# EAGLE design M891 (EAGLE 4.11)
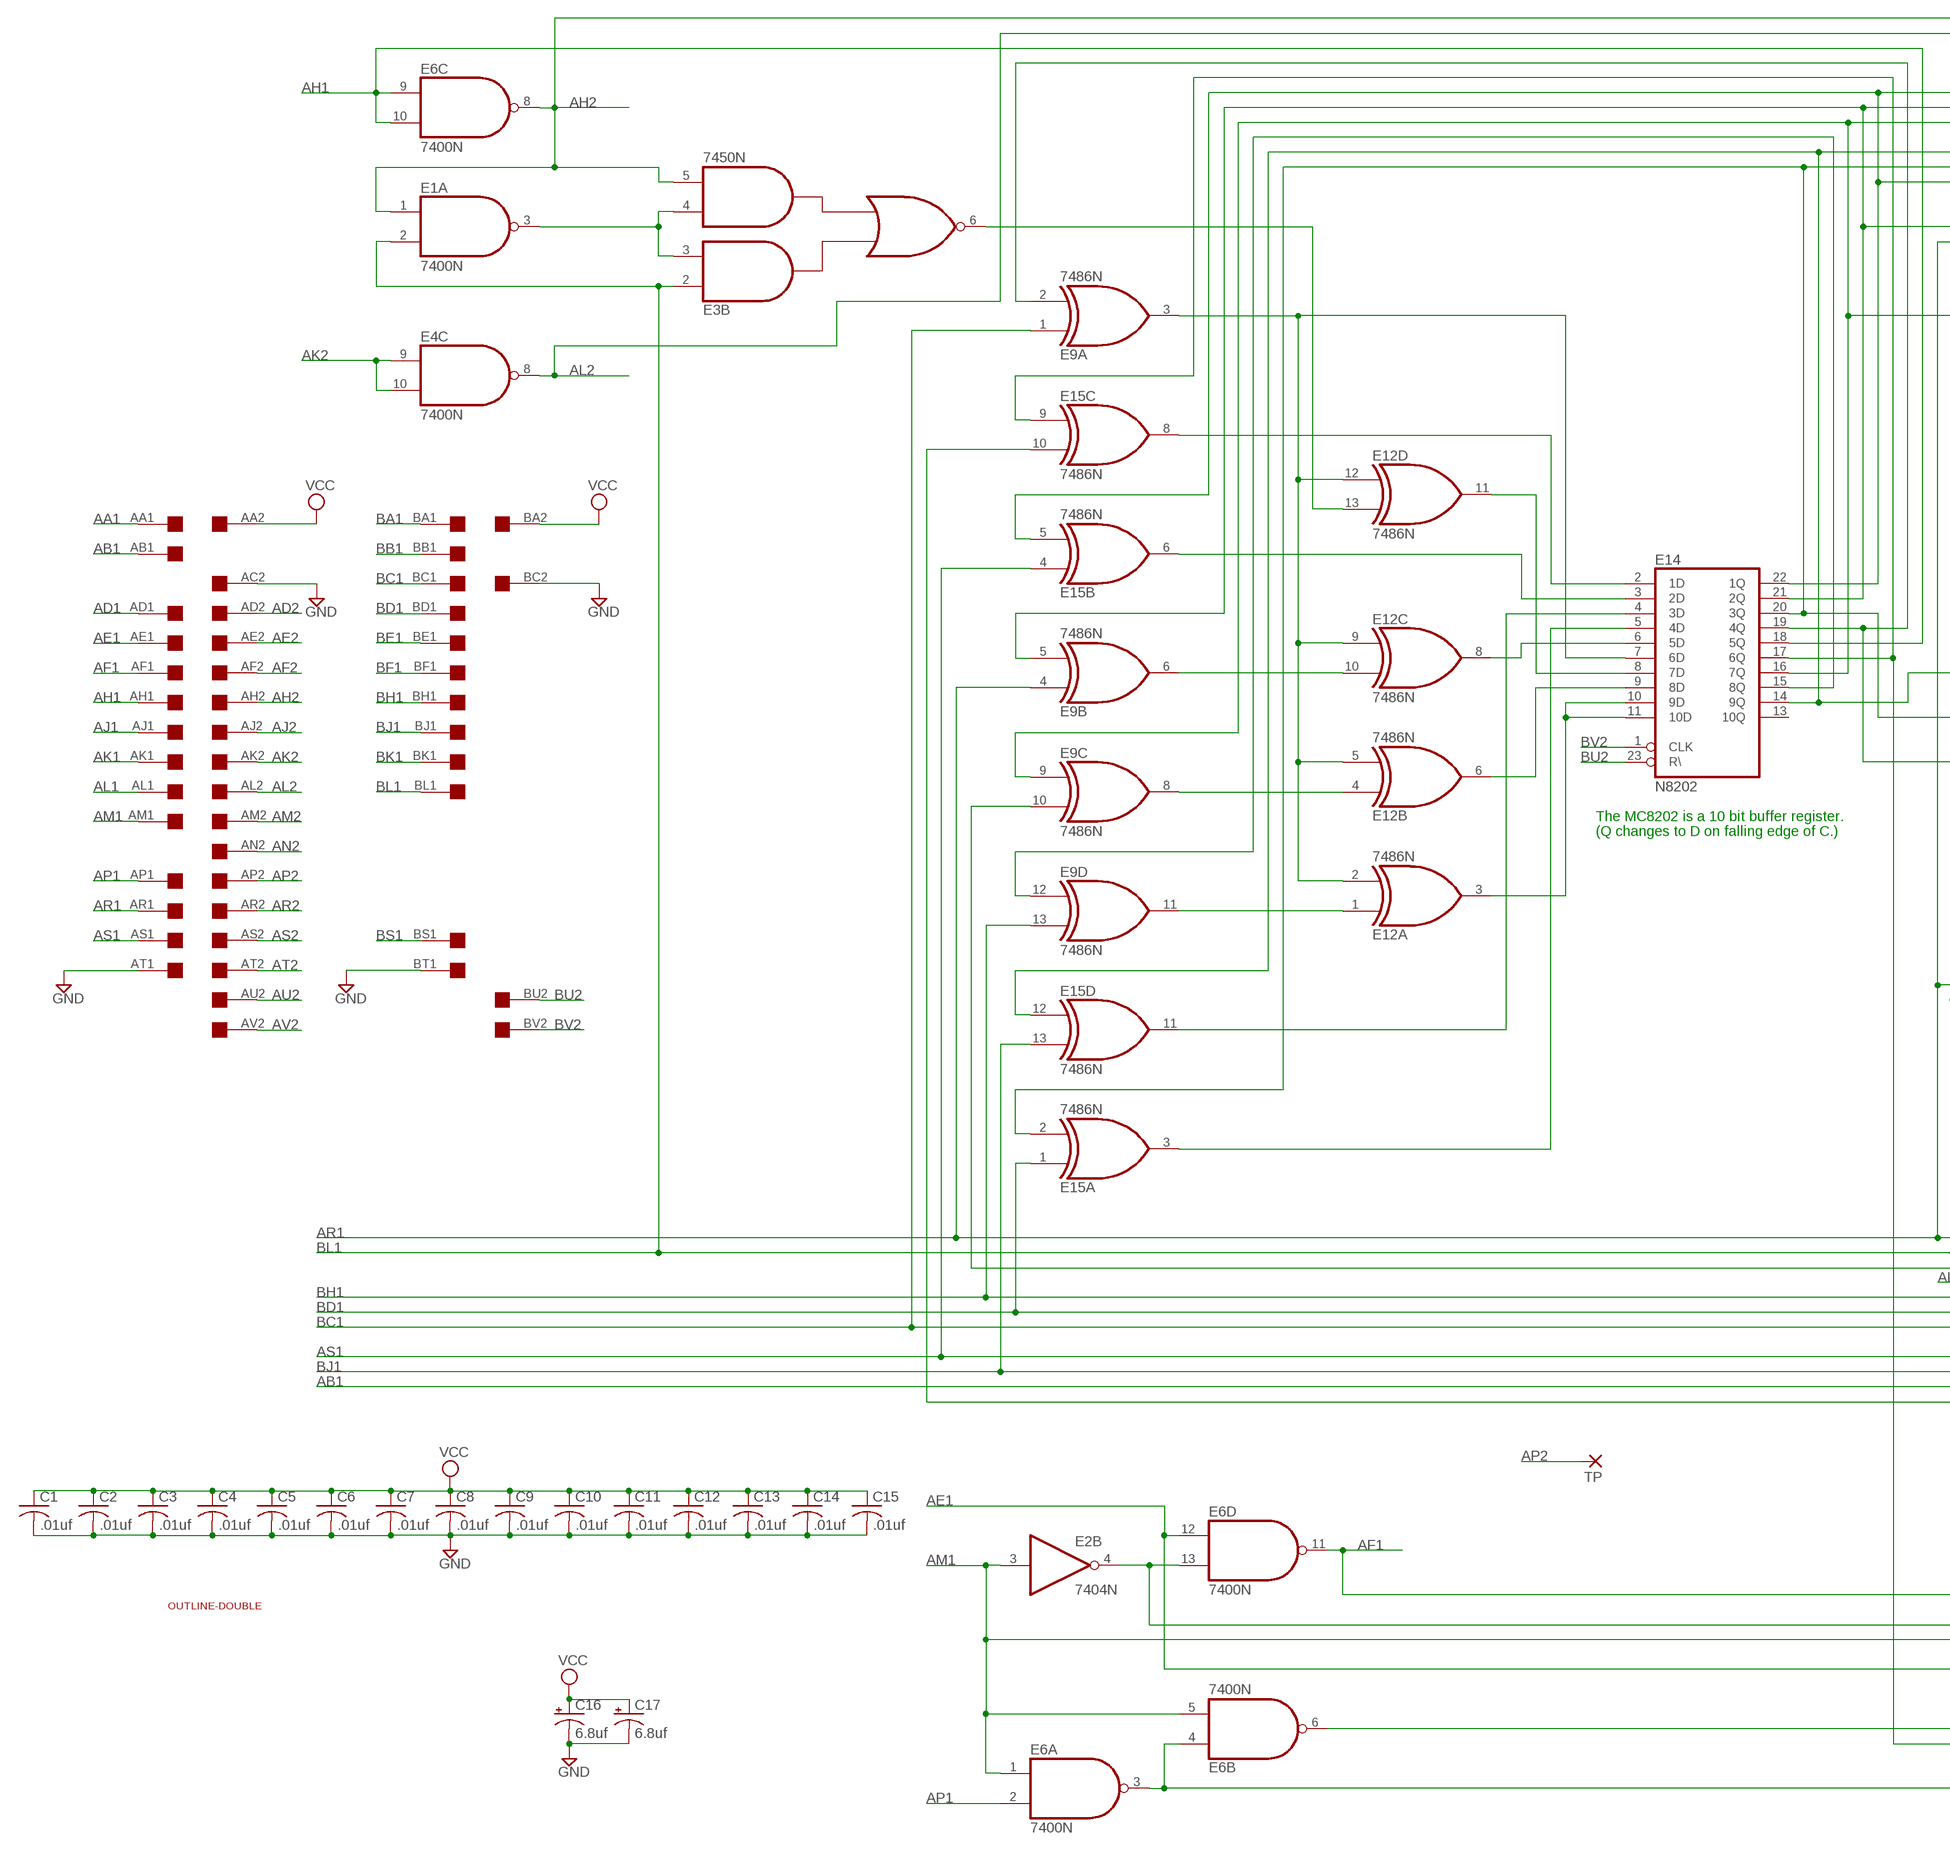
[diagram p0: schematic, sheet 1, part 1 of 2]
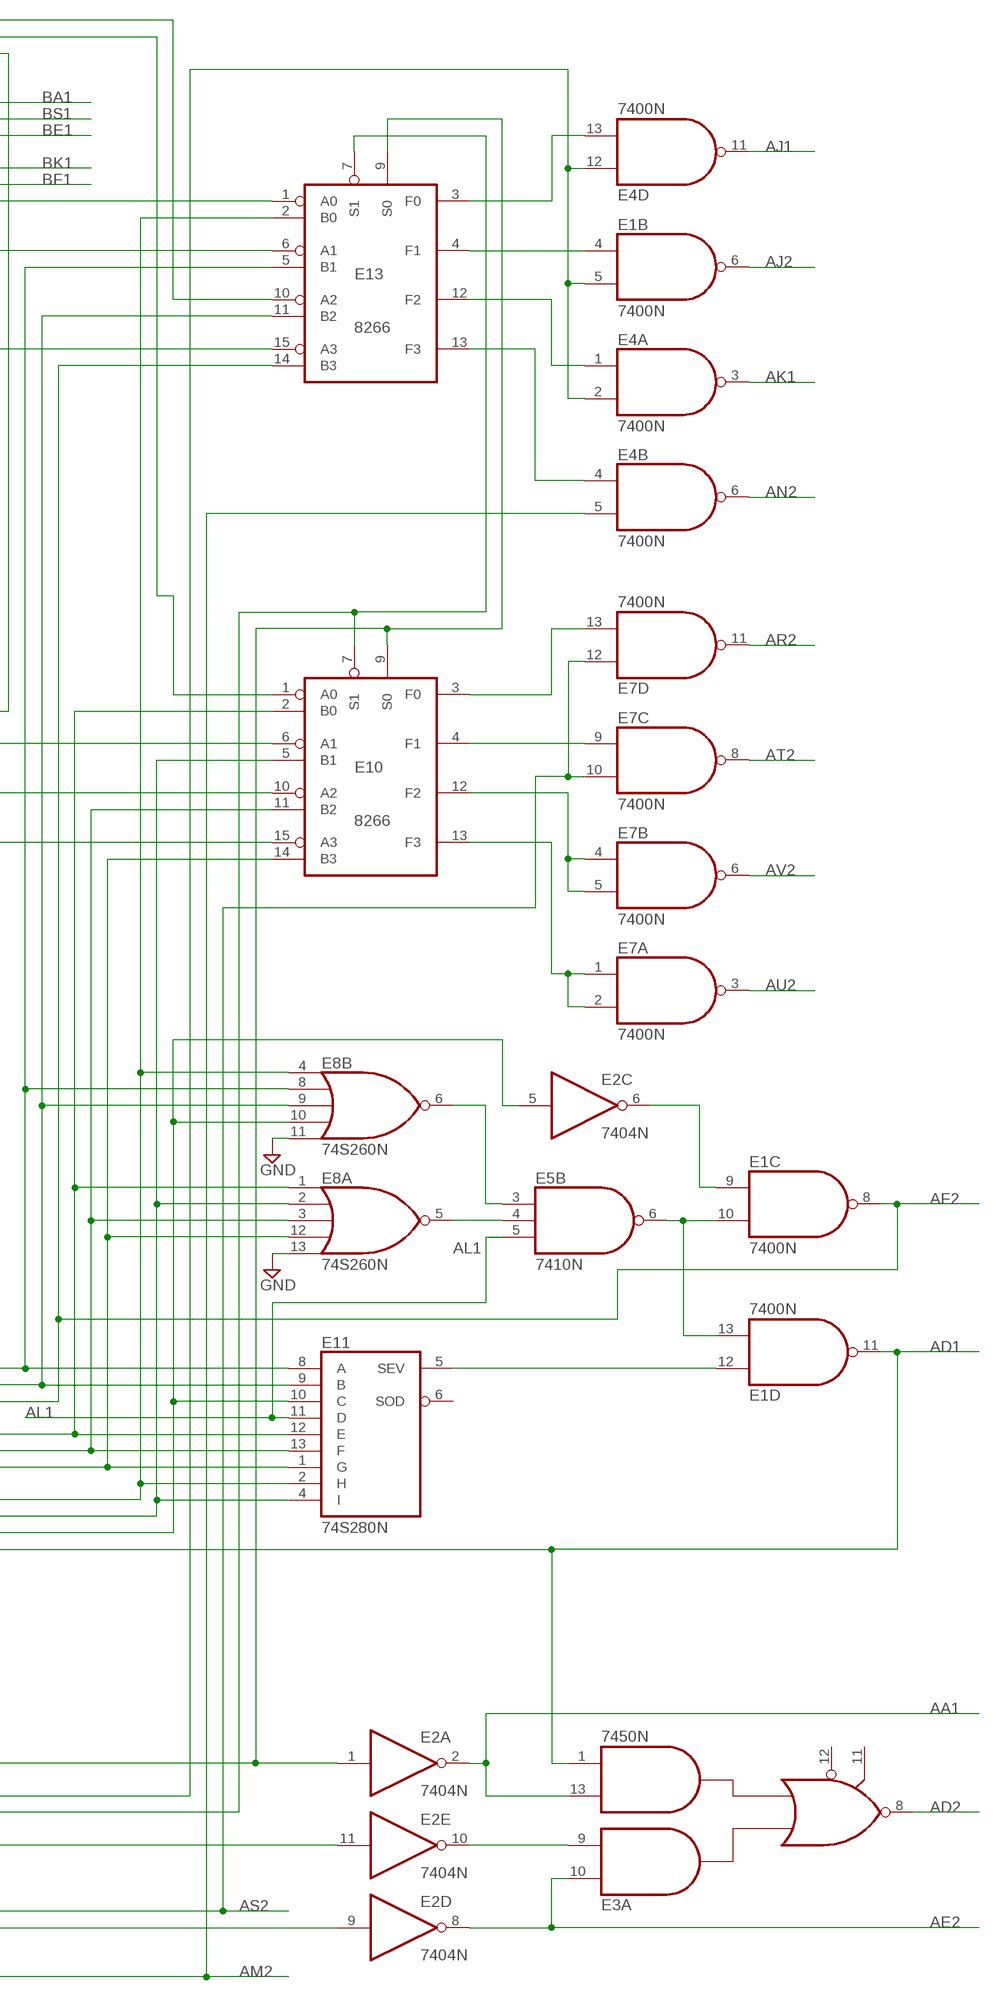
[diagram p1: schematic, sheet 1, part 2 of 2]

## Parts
C1  .01uf  C-US050-025X075  [C050-025X075]
C2  .01uf  C-US050-025X075  [C050-025X075]
C3  .01uf  C-US050-025X075  [C050-025X075]
C4  .01uf  C-US050-025X075  [C050-025X075]
C5  .01uf  C-US050-025X075  [C050-025X075]
C6  .01uf  C-US050-025X075  [C050-025X075]
C7  .01uf  C-US050-025X075  [C050-025X075]
C8  .01uf  C-US050-025X075  [C050-025X075]
C9  .01uf  C-US050-025X075  [C050-025X075]
C10  .01uf  C-US050-025X075  [C050-025X075]
C11  .01uf  C-US050-025X075  [C050-025X075]
C12  .01uf  C-US050-025X075  [C050-025X075]
C13  .01uf  C-US050-025X075  [C050-025X075]
C14  .01uf  C-US050-025X075  [C050-025X075]
C15  .01uf  C-US050-025X075  [C050-025X075]
C16  6.8uf  CPOL-USE22-6AXIAL  [E22-6]
C17  6.8uf  CPOL-USE22-6AXIAL  [E22-6]
E1  7400N  [DIL14]
E2  7404N  [DIL14]
E3  7450N  [DIL14]
E4  7400N  [DIL14]
E5  7410N  [DIL14]
E6  7400N  [DIL14]
E7  7400N  [DIL14]
E8  74S260N  [DIL14]
E9  7486N  [DIL14]
E10  8266  [DIL16]
E11  74S280N  [DIL14]
E12  7486N  [DIL14]
E13  8266  [DIL16]
E14  N8202  [DIL24]
E15  7486N  [DIL14]
EDGE  DOUBLE  [EDGE-CON4]
TP  2,15/1,0  [2,15/1,0]
U$2  OUTLINE-DOUBLE  [DOUBLE]

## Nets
AA1: E2.2(A:O) E3.13(A:I3) EDGE.AA1
AB1: E2.5(C:I) E8.10(B:I3) E11.10(C) EDGE.AB1
AD1: E1.11(D:O) E3.1(A:I4) E15.10(C:I1) EDGE.AD1
AD2: E3.8(A:O) EDGE.AD2
AE1: E2.11(E:I) E6.12(D:I0) EDGE.AE1
AE2: E2.8(D:O) E3.10(A:I1) EDGE.AE2
AF1: E2.1(A:I) E6.11(D:O) E10.9(S0) E13.9(S0) EDGE.AF1
AF2: E1.8(C:O) E9.10(C:I1) E13.14(B3) EDGE.AF2
AH1: E6.9(C:I0) E6.10(C:I1) E14.18(5Q) EDGE.AH1
AH2: E1.1(A:I0) E3.5(B:I4) E6.8(C:O) E13.10(A2) EDGE.AH2
AJ1: E4.11(D:O) EDGE.AJ1
AJ2: E1.6(B:O) EDGE.AJ2
AK1: E4.3(A:O) EDGE.AK1
AK2: E4.9(C:I0) E4.10(C:I1) EDGE.AK2
AL1: E5.5(B:I2) E11.11(D) EDGE.AL1
AL2: E4.8(C:O) E10.1(A0) EDGE.AL2
AM1: E2.3(B:I) E6.1(A:I0) E6.5(B:I1) E10.7(S1) E13.7(S1) EDGE.AM1
AM2: E4.5(B:I1) E6.3(A:O) E6.4(B:I0) EDGE.AM2
AN2: E4.6(B:O) EDGE.AN2
AP1: E6.2(A:I1) EDGE.AP1
AP2: EDGE.AP2 TP.1(P)
AR1: E8.8(B:I1) E9.4(B:I0) E11.8(A) E13.5(B1) EDGE.AR1
AR2: E7.11(D:O) EDGE.AR2
AS1: E8.4(B:I0) E11.2(H) E13.2(B0) E15.4(B:I0) EDGE.AS1
AS2: E6.6(B:O) E7.10(C:I1) E7.12(D:I0) EDGE.AS2
AT2: E7.8(C:O) EDGE.AT2
AU2: E7.3(A:O) EDGE.AU2
AV2: E7.6(B:O) EDGE.AV2
BA1: E13.1(A0) E14.22(1Q) E15.5(B:I1) EDGE.BA1
BB1: E9.2(A:I1) E10.15(A3) E14.19(4Q) EDGE.BB1
BC1: E8.12(A:I3) E9.1(A:I0) E10.14(B3) E11.1(G) EDGE.BC1
BD1: E8.3(A:I2) E10.11(B2) E11.13(F) E15.1(A:I0) EDGE.BD1
BE1: E9.9(C:I0) E13.15(A3) E14.16(7Q) EDGE.BE1
BF1: E10.10(A2) E14.20(3Q) E15.2(A:I1) EDGE.BF1
BH1: E8.1(A:I0) E9.13(D:I1) E10.2(B0) E11.12(E) EDGE.BH1
BJ1: E8.2(A:I1) E10.5(B1) E11.4(I) E15.13(D:I1) EDGE.BJ1
BK1: E10.6(A1) E14.14(9Q) E15.12(D:I0) EDGE.BK1
BL1: E1.2(A:I1) E3.2(B:I1) E8.9(B:I2) E11.9(B) E13.11(B2) EDGE.BL1
BS1: E9.5(B:I1) E13.6(A1) E14.21(2Q) EDGE.BS1
BU2: E14.23(R\) EDGE.BU2
BV2: E14.1(CLK) EDGE.BV2
GND [power]: C1.2 C2.2 C3.2 C4.2 C5.2 C6.2 C7.2 C8.2 C9.2 C10.2 C11.2 C12.2 C13.2 C14.2 C15.2 C16.- C17.- E8.11(B:I4) E8.13(A:I4) EDGE.AC2 EDGE.AT1 EDGE.BC2 EDGE.BT1
N$1: E1.3(A:O) E3.3(B:I2) E3.4(B:I3)
N$4: E2.9(D:I) E14.17(6Q) E15.9(C:I0)
N$5: E1.5(B:I1) E2.4(B:O) E4.2(A:I1) E4.12(D:I0) E6.13(D:I1)
N$6: E4.13(D:I1) E13.3(F0)
N$7: E1.4(B:I0) E13.4(F1)
N$8: E4.1(A:I0) E13.12(F2)
N$9: E4.4(B:I0) E13.13(F3)
N$10: E9.12(D:I0) E14.15(8Q)
N$11: E3.6(B:O) E12.13(D:I1)
N$12: E1.12(D:I0) E11.5(SEV)
N$13: E14.3(2D) E15.6(B:O)
N$14: E9.3(A:O) E12.2(A:I1) E12.5(B:I1) E12.9(C:I0) E12.12(D:I0) E14.7(6D)
N$15: E9.11(D:O) E12.1(A:I0)
N$16: E9.8(C:O) E12.4(B:I0)
N$17: E9.6(B:O) E12.10(C:I1)
N$18: E14.2(1D) E15.8(C:O)
N$19: E12.11(D:O) E14.8(7D)
N$20: E14.5(4D) E15.3(A:O)
N$21: E14.4(3D) E15.11(D:O)
N$22: E12.8(C:O) E14.6(5D)
N$23: E12.6(B:O) E14.9(8D)
N$24: E12.3(A:O) E14.10(9D) E14.11(10D)
N$25: E7.9(C:I0) E10.4(F1)
N$26: E7.13(D:I1) E10.3(F0)
N$27: E7.4(B:I0) E7.5(B:I1) E10.12(F2)
N$28: E7.1(A:I0) E7.2(A:I1) E10.13(F3)
N$33: E2.10(E:O) E3.9(A:I2)
N$43: E5.4(B:I1) E8.5(A:O)
N$44: E5.3(B:I0) E8.6(B:O)
N$45: E1.10(C:I1) E1.13(D:I1) E5.6(B:O)
N$46: E1.9(C:I0) E2.6(C:O)
VCC [power]: C1.1 C2.1 C3.1 C4.1 C5.1 C6.1 C7.1 C8.1 C9.1 C10.1 C11.1 C12.1 C13.1 C14.1 C15.1 C16.+ C17.+ EDGE.AA2 EDGE.BA2
Unconnected: E2.12(F:O) E2.13(F:I) E3.11(A:I6) E3.12(A:I5) E5.1(A:I0) E5.2(A:I1) E5.8(C:O) E5.9(C:I0) E5.10(C:I1) E5.11(C:I2) E5.12(A:O) E5.13(A:I2) E11.6(SOD) E14.13(10Q) EDGE.AB2 EDGE.AC1 EDGE.AN1 EDGE.AU1 EDGE.AV1 EDGE.BB2 EDGE.BD2 EDGE.BE2 EDGE.BF2 EDGE.BH2 EDGE.BJ2 EDGE.BK2 EDGE.BL2 EDGE.BM1 EDGE.BM2 EDGE.BN1 EDGE.BN2 EDGE.BP1 EDGE.BP2 EDGE.BR1 EDGE.BR2 EDGE.BS2 EDGE.BT2 EDGE.BU1 EDGE.BV1

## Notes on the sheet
- The MC8202 is a 10 bit buffer register.
- (Q changes to D on falling edge of C.)

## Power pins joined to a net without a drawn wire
GND: E1.7(P:GND) E2.7(P:GND) E3.7(P:GND) E4.7(P:GND) E5.7(P:GND) E6.7(P:GND) E7.7(P:GND) E8.7(P:GND) E9.7(P:GND) E10.8(GND) E11.7(GND) E12.7(P:GND) E13.8(GND) E14.12(GND) E15.7(P:GND)
VCC: E1.14(P:VCC) E2.14(P:VCC) E3.14(P:VCC) E4.14(P:VCC) E5.14(P:VCC) E6.14(P:VCC) E7.14(P:VCC) E8.14(P:VCC) E9.14(P:VCC) E10.16(VCC) E11.14(VCC) E12.14(P:VCC) E13.16(VCC) E14.24(VCC) E15.14(P:VCC)

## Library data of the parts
C1-C15 = rcl:C-US: CAPACITOR, American symbol
C16 C17 = rcl:CPOL-US: POLARIZED CAPACITOR, American symbol
E1 E4 E6 E7 = 74xx-jameco:74*00: Quad 2-input NAND gate
E2 = 74xx-jameco:74*04: Hex INVERTER
E3 = 74xxN:74*50: 4-2-3-2 input AND OR INVERTER gates
E5 = 74xx-jameco:74*10: Triple 3-input NAND gate
E8 = 74xx-jameco:74*260: Dual 5-input positive NOR gate
E9 E12 E15 = 74xx-jameco:74*86: Quad 2-input EXCLUSIV-OR (XOR) gate
E10 E13 = dec-con:8266: Quad 2-1 selector
E11 = 74xx-jameco:74*280: 9-bit odd/even PARITY GENERATOR/CHECKER
E14 = dec-con:N8202: 10 bit register
EDGE = dec-con:DOUBLE: Double-Height DEC board
TP = wirepad:2,15/1,0: THROUGH-HOLE PAD
U$2 = dec-con:OUTLINE-*: Board outlines for DEC boards.

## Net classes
1 power: width 0.508 mm

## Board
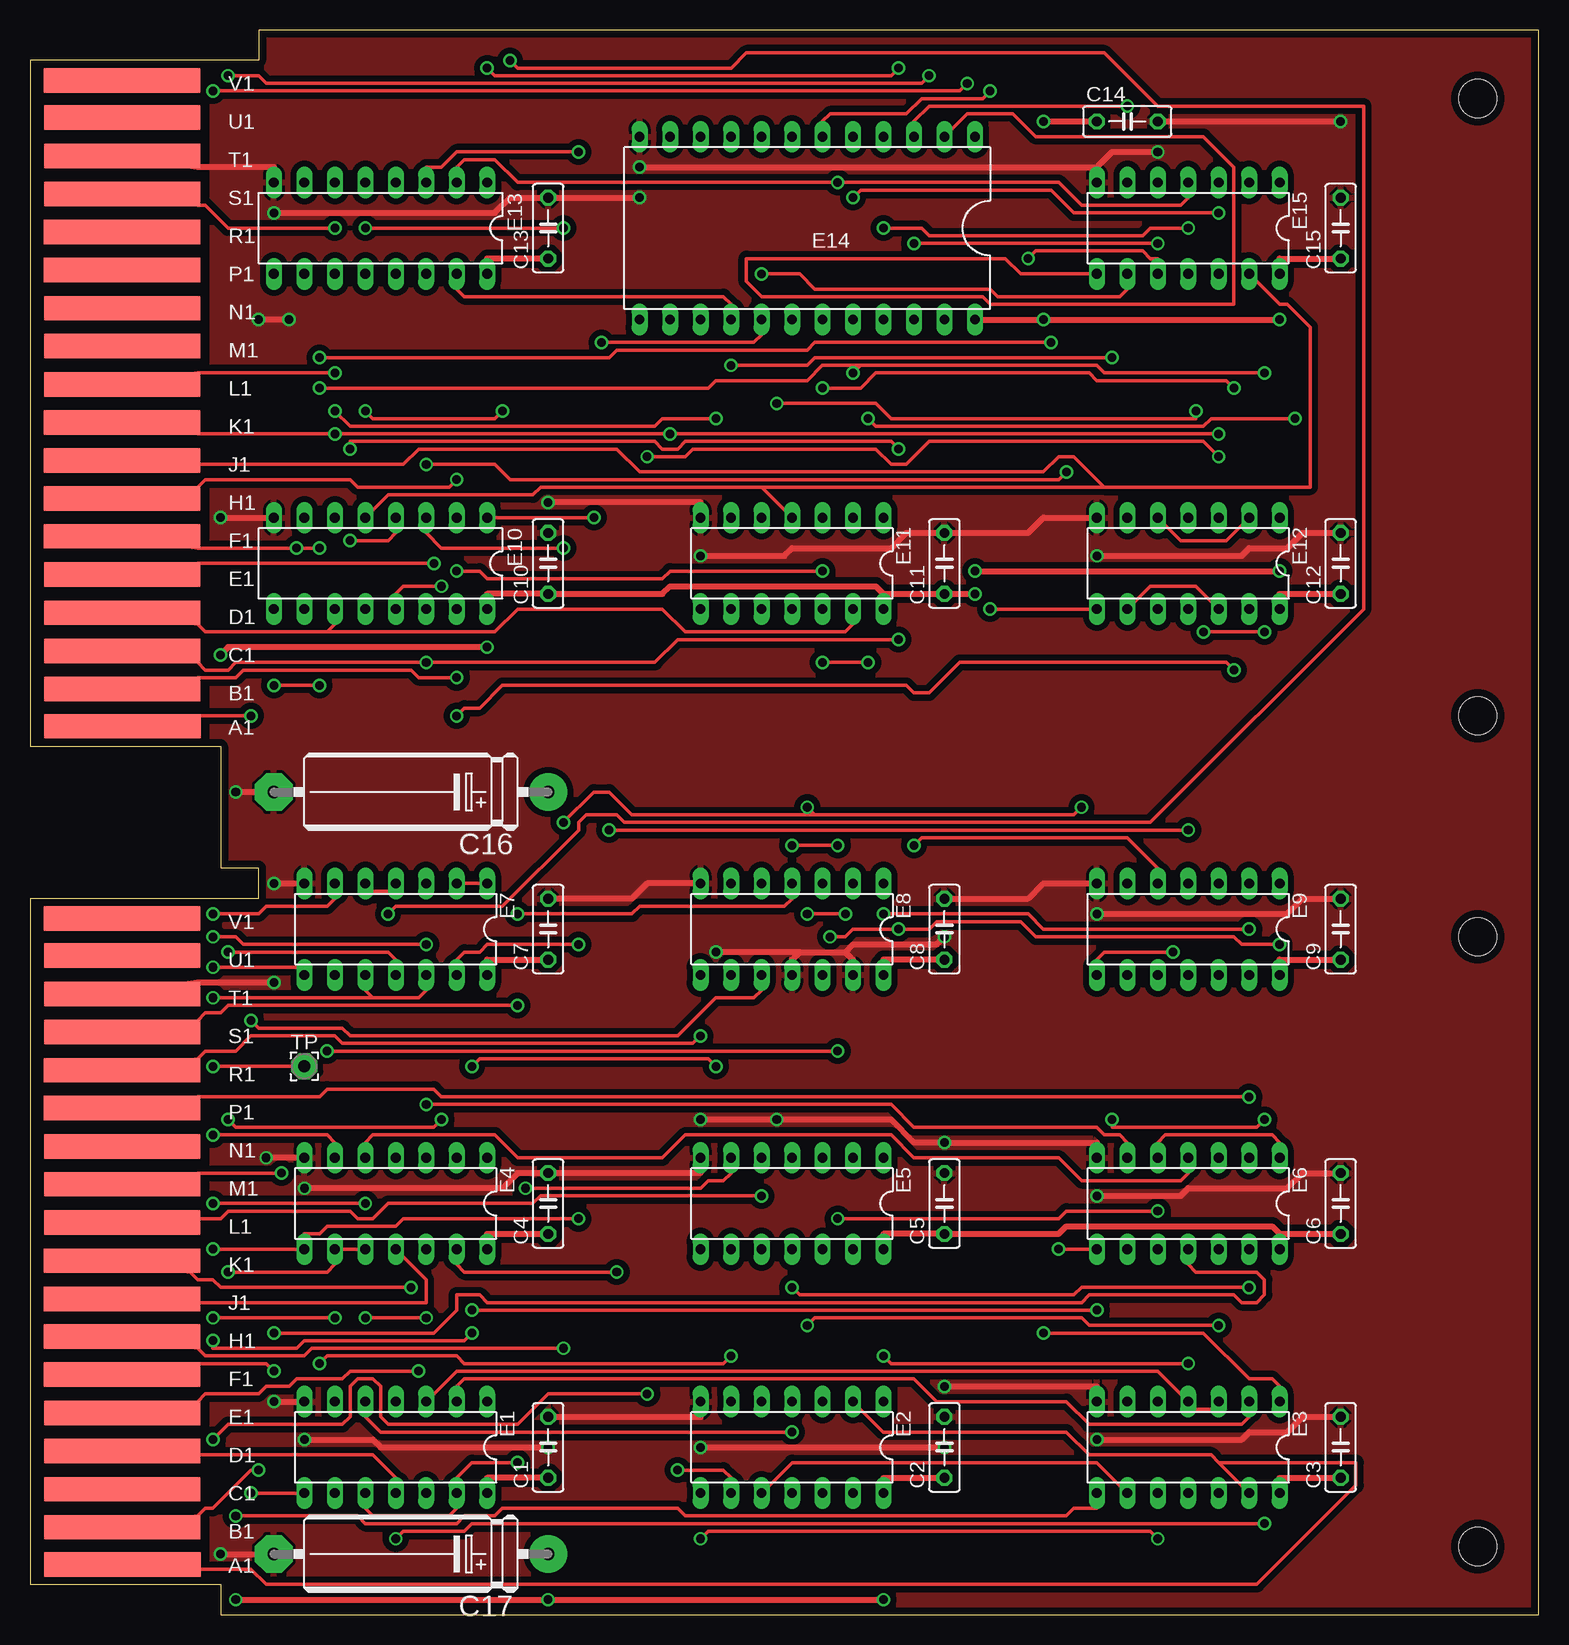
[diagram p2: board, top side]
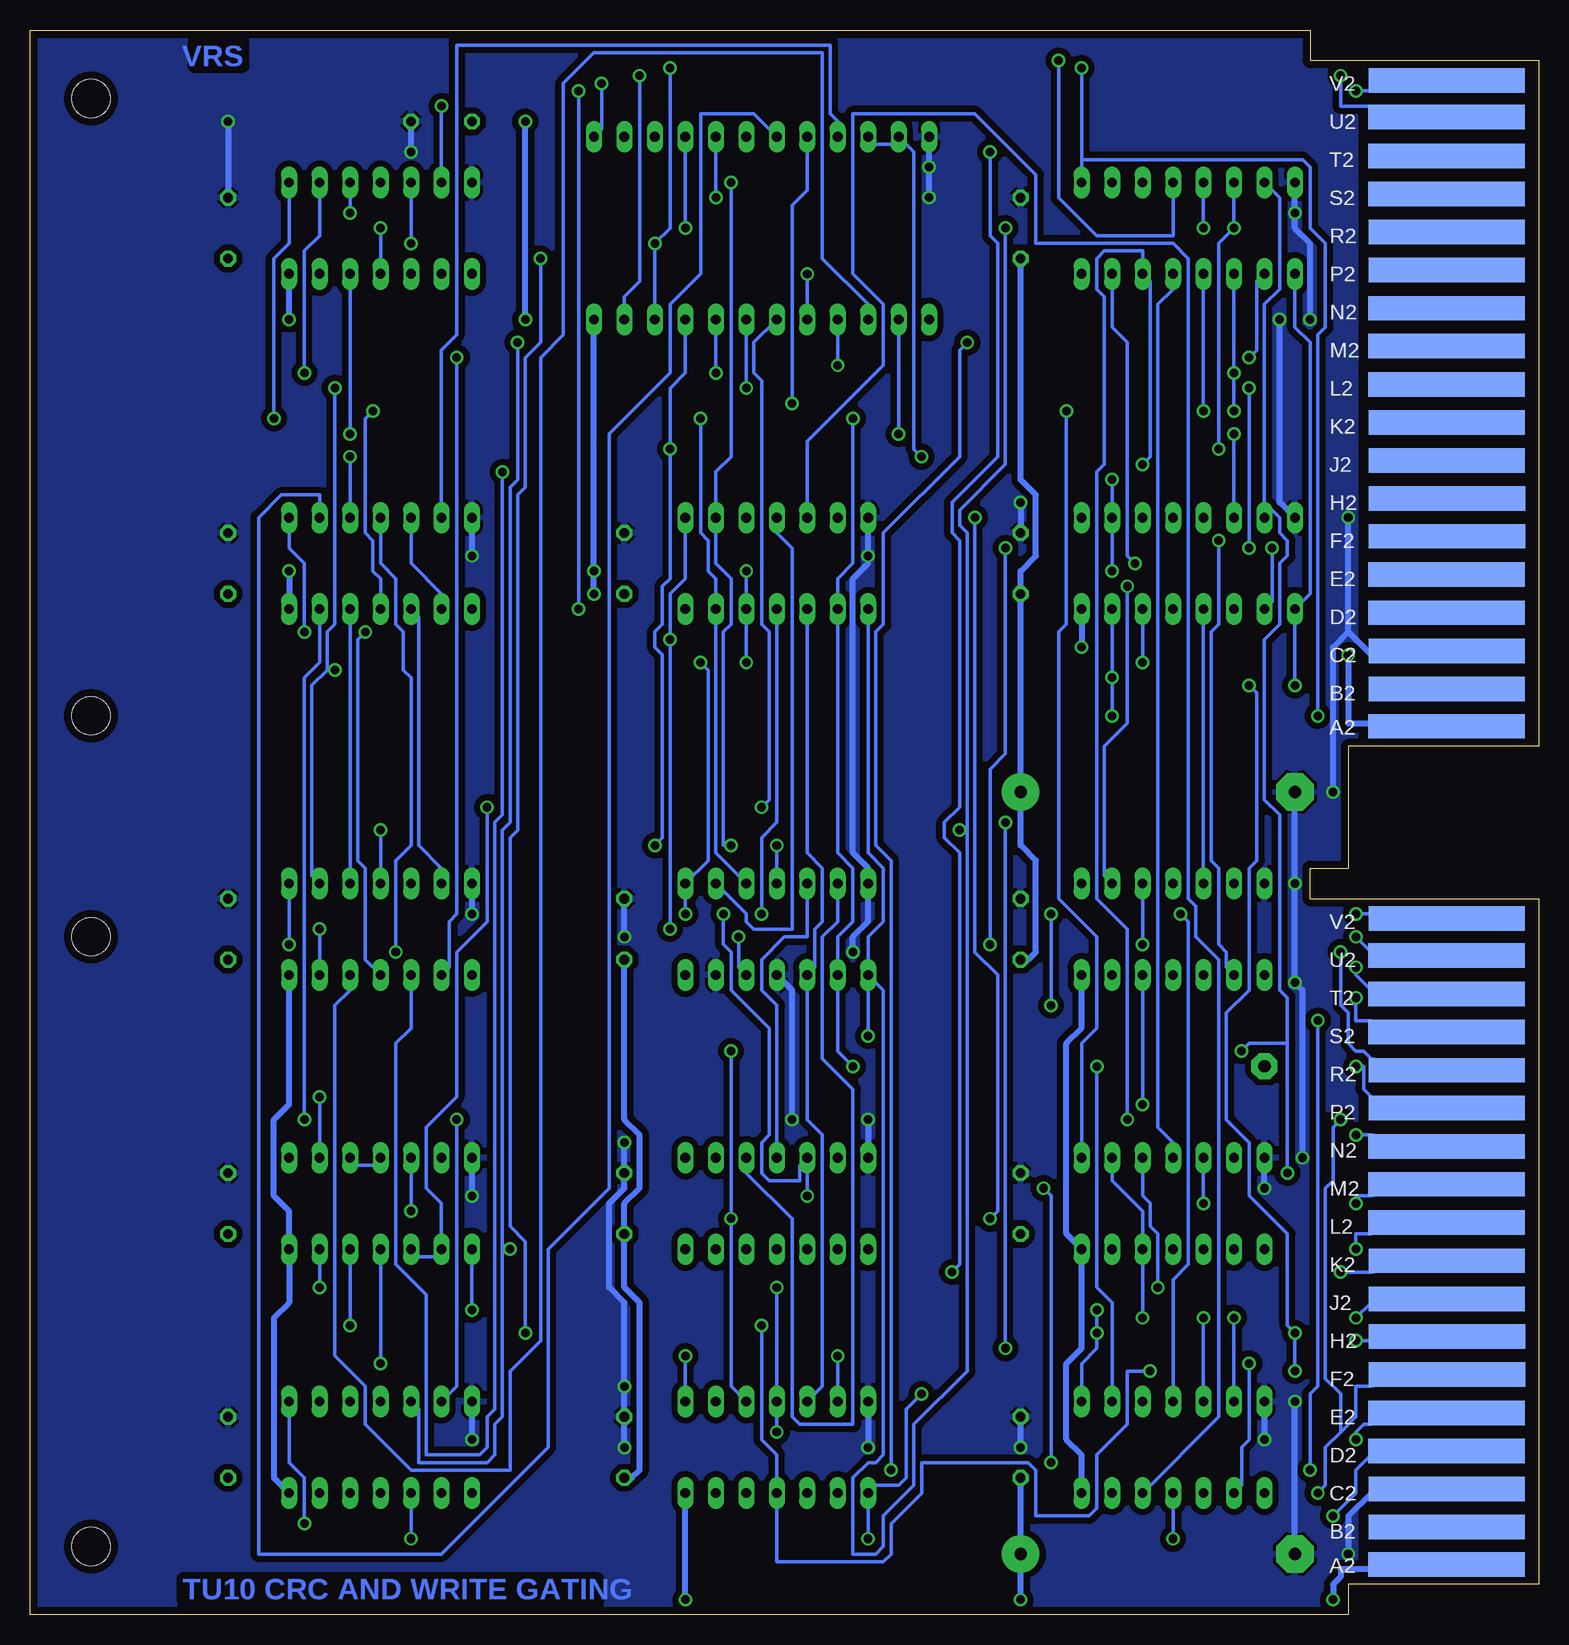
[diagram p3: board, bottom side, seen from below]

Size 125.73 x 132.08 mm. Coordinates in mm from the lower left corner, seen from the top.
Copper layers (1*16): Top 0.035mm / dielectric 1.5mm / Bottom 0.035mm
Design rules "10mils": minimum track width 12mil, minimum drill 28mil, track to track 10mil, track to pad 10mil, pad to pad 10mil, via to via 10mil, smd to smd 10mil, copper to edge 25mil, drill to drill 10mil, minimum pad ring 10mil, minimum via ring 8mil, stop-mask expansion 0mil, vias tented up to drill 0mil, thermal gap 10mil

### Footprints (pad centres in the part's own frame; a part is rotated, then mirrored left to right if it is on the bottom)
C050-025X075 = drill 0.813 octagon: 1 -2.54,0; 2 2.54,0
E22-6 = drill 1.016 pad 3.15 round: + -11.43,0 | drill 1.016 pad 3.15 octagon: - 11.43,0
DIL14 = drill 0.813 long: 1 -7.62,-3.81; 2 -5.08,-3.81; 3 -2.54,-3.81; 4 0,-3.81; 5 2.54,-3.81; 6 5.08,-3.81; 7 7.62,-3.81; 8 7.62,3.81; 9 5.08,3.81; 10 2.54,3.81; 11 0,3.81; 12 -2.54,3.81; 13 -5.08,3.81; 14 -7.62,3.81
DIL16 = drill 0.813 long: 1 -8.89,-3.81; 2 -6.35,-3.81; 3 -3.81,-3.81; 4 -1.27,-3.81; 5 1.27,-3.81; 6 3.81,-3.81; 7 6.35,-3.81; 8 8.89,-3.81; 9 8.89,3.81; 10 6.35,3.81; 11 3.81,3.81; 12 1.27,3.81; 13 -1.27,3.81; 14 -3.81,3.81; 15 -6.35,3.81; 16 -8.89,3.81
DIL24 = drill 0.813 long: 1 -12.7,-7.62; 2 -10.16,-7.62; 3 -7.62,-7.62; 4 -5.08,-7.62; 5 -2.54,-7.62; 6 0,-7.62; 7 2.54,-7.62; 8 5.08,-7.62; 9 7.62,-7.62; 10 10.16,-7.62; 11 12.7,-7.62; 12 15.24,-7.62; 13 15.24,7.62; 14 12.7,7.62; 15 10.16,7.62; 16 7.62,7.62; 17 5.08,7.62; 18 2.54,7.62; 19 0,7.62; 20 -2.54,7.62; 21 -5.08,7.62; 22 -7.62,7.62; 23 -10.16,7.62; 24 -12.7,7.62
EDGE-CON4 = smd 13.017 x 2.032: AA1 7.709,4.207; AB1 7.684,7.312; AC1 7.684,10.474; AD1 7.684,13.665; AE1 7.693,16.84; AF1 7.668,20.041; AH1 7.668,23.19; AJ1 7.668,26.34; AK1 7.668,29.515; AL1 7.693,32.69; AM1 7.693,35.89; AN1 7.693,39.04; AP1 7.668,42.24; AR1 7.668,45.39; AS1 7.693,48.565; AT1 7.693,51.74; AU1 7.693,54.94; AV1 7.668,58.026; BA1 7.709,74.057; BB1 7.684,77.162; BC1 7.684,80.324; BD1 7.684,83.515; BE1 7.693,86.69; BF1 7.668,89.891; BH1 7.668,93.04; BJ1 7.668,96.19; BK1 7.668,99.365; BL1 7.693,102.54; BM1 7.693,105.74; BN1 7.693,108.89; BP1 7.668,112.09; BR1 7.668,115.24; BS1 7.693,118.415; BT1 7.693,121.59; BU1 7.693,124.79; BV1 7.668,127.876 | smd 13.017 x 2.032 bottom: AA2 7.69,4.207; AB2 7.668,7.328; AC2 7.668,10.49; AD2 7.693,13.665; AE2 7.693,16.84; AF2 7.642,20.041; AH2 7.642,23.19; AJ2 7.668,26.34; AK2 7.668,29.515; AL2 7.693,32.69; AM2 7.693,35.89; AN2 7.693,39.04; AP2 7.668,42.24; AR2 7.668,45.39; AS2 7.693,48.565; AT2 7.693,51.74; AU2 7.693,54.966; AV2 7.668,58.026; BA2 7.69,74.057; BB2 7.668,77.178; BC2 7.668,80.34; BD2 7.693,83.515; BE2 7.693,86.69; BF2 7.642,89.891; BH2 7.642,93.04; BJ2 7.668,96.19; BK2 7.668,99.365; BL2 7.693,102.54; BM2 7.693,105.74; BN2 7.693,108.89; BP2 7.668,112.09; BR2 7.668,115.24; BS2 7.693,118.415; BT2 7.693,121.59; BU2 7.693,124.816; BV2 7.668,127.876
2,15/1,0 = drill 1.016 pad 2.159 octagon: 1 0,0
DOUBLE = hole 3.175: 120.65,56.515; 120.65,5.715; 120.65,74.93; 120.65,126.365

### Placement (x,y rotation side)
C1  43.18,13.97 90 top
C2  76.2,13.97 90 top
C3  109.22,13.97 90 top
C4  43.18,34.29 90 top
C5  76.2,34.29 90 top
C6  109.22,34.29 90 top
C7  43.18,57.15 90 top
C8  76.2,57.15 90 top
C9  109.22,57.15 90 top
C10  43.18,87.63 90 top
C11  76.2,87.63 90 top
C12  109.22,87.63 90 top
C13  43.18,115.57 90 top
C14  91.44,124.46 0 top
C15  109.22,115.57 90 top
C16  31.75,68.58 180 top
C17  31.75,5.08 180 top
E1  30.48,13.97 180 top
E2  63.5,13.97 180 top
E3  96.52,13.97 180 top
E4  30.48,34.29 180 top
E5  63.5,34.29 180 top
E6  96.52,34.29 180 top
E7  30.48,57.15 180 top
E8  63.5,57.15 180 top
E9  96.52,57.15 180 top
E10  29.21,87.63 180 top
E11  63.5,87.63 180 top
E12  96.52,87.63 180 top
E13  29.21,115.57 180 top
E14  66.04,115.57 180 top
E15  96.52,115.57 180 top
EDGE  0,0 0 top
TP  22.86,45.72 0 top
U$2  0,0 0 top

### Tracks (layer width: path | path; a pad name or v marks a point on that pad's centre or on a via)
AA1
  Top 0.305: 99.06,12.7 98.43,13.34 88.27,13.34 86.36,15.24 71.12,15.24 E2.2 | 99.06,12.7 E3.13 | 99.06,12.7 110.49,12.7 110.49,10.79 102.24,2.54 19.69,2.54 18.42,3.81 13.97,3.81 EDGE.AA1
AB1  (via drill 0.71)
  Top 0.305: v19.05,12.06 18.42,12.06 15.24,8.89 14.61,8.89 13.97,8.26 EDGE.AB1 | v18.42,49.53 19.05,48.9 26.04,48.9 26.67,48.26 53.98,48.26 57.15,51.44 60.33,51.44 60.96,52.07 E8.10
  Bottom 0.305: v19.05,12.06 19.05,18.41 18.42,19.05 v18.42,49.53 | E2.5 59.69,19.05 59.69,40.01 60.96,41.27 E8.10 60.33,53.98 60.33,57.15 59.69,57.78 59.69,62.23 60.96,63.5 E11.10
AD1  (via drill 0.71)
  Top 0.305: E1.11 30.48,11.43 28.58,13.34 13.97,13.34 EDGE.AD1 | v102.87,7.62 36.83,7.62 36.2,6.99 31.12,6.99 v30.48,6.35 | v83.19,113.03 83.82,113.67 92.71,113.67 93.35,113.03 93.98,113.03 E15.10 | v84.46,23.5 97.79,23.5 101.6,19.68 103.51,19.68 104.14,19.05 E3.1
  Bottom 0.305: v102.87,7.62 102.87,11.43 104.14,12.7 E3.1 | E1.11 v30.48,6.35 | v83.19,113.03 83.19,106.05 84.46,104.78 84.46,93.98 85.09,93.34 85.09,65.41 85.73,64.77 85.73,32.38 84.46,31.11 v84.46,23.5
AD2  (via drill 0.71)
  Top 0.305: v17.15,8.26 27.31,8.26 27.94,7.62 35.56,7.62 36.2,8.26 38.74,8.26 39.37,8.89 53.98,8.89 54.61,8.26 86.36,8.26 87,8.89 88.9,8.89 E3.8
  Bottom 0.305: v17.15,8.26 15.24,10.16 15.24,12.06 13.97,13.34 EDGE.AD2
AE1  (via drill 0.71)
  Top 0.305: v32.39,20.32 26.67,20.32 26.04,19.68 22.23,19.68 21.59,19.05 19.69,19.05 19.05,18.41 14.61,18.41 13.97,17.78 EDGE.AE1 | v99.06,24.13 88.27,24.13 87.63,24.77 65.41,24.77 v64.77,24.13
  Bottom 0.305: v32.39,20.32 34.29,20.32 34.29,15.88 36.83,13.34 36.83,8.89 37.47,8.26 41.91,8.26 41.91,12.06 42.55,12.7 51.44,12.7 51.44,10.16 53.98,7.62 53.98,5.08 54.61,4.45 63.5,4.45 E2.11 63.5,13.34 64.77,14.61 v64.77,24.13 | v99.06,24.13 E6.12
AE2  (via drill 0.71)
  Top 0.305: v15.24,14.61 16.51,15.88 26.04,15.88 26.67,16.51 26.67,19.05 27.31,19.68 28.58,19.68 29.21,19.05 29.21,16.51 29.85,15.88 40.64,15.88 43.18,18.41 v51.44,18.41 | v93.98,6.35 93.35,6.99 56.52,6.99 v55.88,6.35
  Bottom 0.305: v15.24,14.61 15.24,15.24 14.61,15.88 13.97,15.88 EDGE.AE2 | v51.44,18.41 52.71,17.14 52.71,11.43 53.34,10.79 55.25,10.79 E2.8 v55.88,6.35 | v93.98,6.35 E3.10
AF1  (via drill 0.71)
  Top 0.305: v20.32,20.32 19.69,20.95 13.97,20.95 EDGE.AF1 | v20.32,23.5 33.66,23.5 35.56,25.4 35.56,26.67 37.47,26.67 38.1,26.04 87.63,26.04 88.27,26.67 100.33,26.67 100.97,26.04 102.24,26.04 102.87,26.67 102.87,27.94 102.24,28.57 97.16,28.57 96.52,29.21 E6.11 | v71.12,21.59 71.76,20.95 v96.52,20.95 | v24.13,77.47 v20.32,77.47
  Bottom 0.305: E13.9 20.32,107.31 19.05,106.05 19.05,85.09 E10.9 v20.32,77.47 | v20.32,20.32 v20.32,23.5 20.96,24.13 20.96,31.75 24.13,34.92 24.13,39.37 26.04,41.27 26.04,50.16 24.13,52.07 24.13,62.23 23.5,62.87 23.5,76.83 v24.13,77.47 | v71.12,21.59 E2.1 | E6.11 v96.52,20.95
AF2  (via drill 0.71)
  Top 0.305: v18.42,10.16 E1.8 | v33.02,95.89 38.74,95.89 40.01,94.61 85.73,94.61 v86.36,95.25 | v16.51,41.27 17.15,40.64 33.66,40.64 v34.29,41.27
  Bottom 0.305: 16.51,15.24 17.78,13.97 17.78,10.79 v18.42,10.16 | 16.51,15.24 15.24,16.51 15.24,19.05 13.97,19.05 EDGE.AF2 | v33.02,95.89 32.39,96.52 32.39,111.12 E13.14 33.02,113.67 36.2,113.67 36.83,113.03 36.83,110.49 36.2,109.86 36.2,95.89 36.83,95.25 36.83,59.69 34.29,57.15 v34.29,41.27 | v86.36,95.25 86.36,66.67 87,66.04 87,17.14 87.63,16.51 87.63,13.97 88.27,13.34 92.71,13.34 92.71,26.67 95.25,29.21 95.25,47.62 93.98,48.9 E9.10 | 16.51,15.24 16.51,18.41 17.78,19.68 17.78,35.56 17.15,36.2 17.15,40.64 v16.51,41.27
AH1  (via drill 0.71)
  Top 0.305: 65.41,66.67 v64.77,67.31 | 65.41,66.67 87,66.67 v87.63,67.31 | v44.45,22.23 23.5,22.23 22.86,21.59 14.61,21.59 13.97,22.23 EDGE.AH1 | v44.45,66.04 46.99,68.58 48.26,68.58 50.17,66.67 65.41,66.67
  Bottom 0.305: E6.10 93.35,29.84 92.08,29.84 E6.9 91.44,34.29 92.71,35.56 92.71,40.64 90.17,43.18 90.17,55.24 87.63,57.78 v87.63,67.31 | v64.77,67.31 64.14,67.94 64.14,81.92 64.77,82.55 64.77,102.87 65.41,103.5 65.41,106.05 E14.18 | v44.45,22.23 v44.45,66.04
AH2  (via drill 0.71)
  Top 0.305: v15.24,22.86 15.24,22.23 22.23,22.23 22.86,22.86 36.2,22.86 v36.83,23.5 | v24.13,104.78 48.26,104.78 48.9,105.41 64.77,105.41 65.41,106.05 v85.09,106.05 | E6.8 v85.73,30.48 | v36.83,25.4 v88.9,25.4
  Bottom 0.305: v15.24,22.86 13.97,22.86 EDGE.AH2 | E1.1 38.1,20.95 36.83,22.23 v36.83,23.5 v36.83,25.4 | v24.13,104.78 23.5,105.41 23.5,111.12 E13.10 | v85.09,106.05 85.09,94.61 85.73,93.98 85.73,66.04 86.36,65.41 86.36,30.48 | 86.36,30.48 86.36,16.51 87,15.88 87,13.34 87.63,12.7 93.35,12.7 93.35,17.14 E3.5 | v85.73,30.48 86.36,30.48 | v88.9,25.4 E6.8
AJ1
  Top 0.305: E4.11 33.02,27.94 33.02,26.04 13.97,26.04 EDGE.AJ1
AJ2  (via drill 0.71)
  Top 0.305: v15.24,24.77 v25.4,24.77
  Bottom 0.305: v15.24,24.77 13.97,26.04 EDGE.AJ2 | v25.4,24.77 E1.6
AK1  (via drill 0.71)
  Top 0.305: v31.75,27.3 15.88,27.3 15.24,27.94 13.97,27.94 13.34,28.57 EDGE.AK1
  Bottom 0.305: v31.75,27.3 31.75,31.75 32.39,32.38 32.39,34.29 33.02,34.92 E4.3
AK2  (via drill 0.71)
  Top 0.305: v16.51,28.57 24.77,28.57 25.4,29.21 E4.9 E4.10
  Bottom 0.305: v16.51,28.57 13.97,28.57 EDGE.AK2
AL1  (via drill 0.71)
  Top 0.305: v60.96,34.92 42.55,34.92 41.91,34.29 29.85,34.29 28.58,33.02 27.31,33.02 26.67,33.66 16.51,33.66 15.88,33.02 13.97,33.02 EDGE.AL1 | v67.95,58.42 v64.77,58.42
  Bottom 0.305: v60.96,34.92 E5.5 61.6,37.47 61.6,36.2 64.14,36.2 64.77,36.83 64.77,39.37 64.14,40.01 64.14,48.9 67.31,52.07 67.31,55.24 67.95,55.88 v67.95,58.42 | v64.77,58.42 64.77,64.77 63.5,66.04 E11.11
AL2  (via drill 0.71)
  Top 0.305: v15.24,30.48 E4.8 22.86,31.75 24.13,31.75 24.77,32.38 30.48,32.38 31.12,33.02 v45.72,33.02 | v46.99,91.44 E10.1
  Bottom 0.305: v15.24,30.48 15.24,31.75 13.97,31.75 EDGE.AL2 | v46.99,91.44 46.99,55.24 45.09,53.34 45.09,33.66 v45.72,33.02
AM1  (via drill 0.71)
  Top 0.305: v67.31,33.02 85.73,33.02 86.36,33.66 v93.98,33.66 | E6.1 104.14,39.37 103.51,40.01 94.62,40.01 93.98,39.37 E6.5 | v20.96,36.83 13.97,36.83 EDGE.AM1 | v24.77,46.99 v67.31,46.99
  Bottom 0.305: E2.3 67.31,19.05 v67.31,33.02 v67.31,46.99 | v93.98,33.66 E6.5 | 20.96,47.62 20.96,51.44 21.59,52.07 21.59,66.67 22.86,67.94 22.86,81.28 21.59,82.55 21.59,87.63 20.96,88.27 20.96,89.53 21.59,90.17 21.59,91.44 22.23,92.08 E10.7 22.86,109.22 21.59,110.49 21.59,118.11 E13.7 | v20.96,36.83 20.96,47.62 | v24.77,46.99 24.13,47.62 20.96,47.62
AM2  (via drill 0.71)
  Top 0.305: E6.4 96.52,36.83 95.89,36.2 87.63,36.2 85.73,38.1 73.66,38.1 71.76,40.01 54.61,40.01 52.71,38.1 40.64,38.1 38.74,40.01 28.58,40.01 27.94,39.37 E4.5 | v15.24,34.29 v27.94,34.29
  Bottom 0.305: E6.3 98.43,37.47 97.16,37.47 E6.4 | v15.24,34.29 15.24,34.92 13.97,34.92 EDGE.AM2 | v27.94,34.29 E4.5
AN2  (via drill 0.71)
  Top 0.305: v15.24,40.01 24.77,40.01 25.4,39.37 E4.6
  Bottom 0.305: v15.24,40.01 13.97,40.01 EDGE.AN2
AP1  (via drill 0.71)
  Top 0.305: v101.6,43.18 34.29,43.18 33.66,43.81 24.77,43.81 24.13,43.18 13.97,43.18 EDGE.AP1
  Bottom 0.305: v101.6,43.18 E6.2
AP2  (via drill 0.71)
  Top 0.305: v15.24,45.72 TP.1
  Bottom 0.305: v15.24,45.72 14.61,45.72 14.61,43.81 13.97,43.18 EDGE.AP2
AR1  (via drill 0.71)
  Top 0.305: v55.88,48.26 55.25,47.62 26.04,47.62 25.4,48.26 18.42,48.26 17.15,46.99 14.61,46.99 13.97,46.35 EDGE.AR1 | v44.45,115.57 v27.94,115.57 | v48.26,65.41 v96.52,65.41
  Bottom 0.305: v55.88,48.26 E8.8 | E11.8 55.88,63.5 54.61,62.23 54.61,57.78 55.88,56.52 E8.8 | v44.45,115.57 44.45,95.89 48.26,92.08 48.26,90.81 47.63,90.17 47.63,65.41 | 47.63,65.41 47.63,20.32 52.07,15.88 52.07,10.79 54.61,8.26 54.61,5.71 55.25,5.08 57.15,5.08 57.15,11.43 55.88,12.7 55.25,12.7 54.61,13.34 54.61,52.07 E8.8 | v27.94,115.57 E13.5 | 47.63,65.41 v48.26,65.41 | v96.52,65.41 E9.4
AR2  (via drill 0.71)
  Top 0.305: v16.51,55.24 29.85,55.24 30.48,54.61 E7.11
  Bottom 0.305: v16.51,55.24 16.51,50.8 15.88,50.16 15.88,47.62 15.24,46.99 14.61,46.99 13.97,46.35 EDGE.AR2
AS1  (via drill 0.71)
  Top 0.305: E15.4 96.52,118.11 95.89,117.47 87.63,117.47 85.73,119.38 v67.31,119.38 40.64,119.38 38.74,121.28 36.2,121.28 35.56,120.65 E13.2 | v63.5,64.14 v67.31,64.14 | v40.64,50.8 16.51,50.8 15.88,50.16 14.61,50.16 13.97,49.53 EDGE.AS1 | v40.64,58.42 50.17,58.42 50.8,59.05 62.87,59.05 63.5,59.69 E8.4
  Bottom 0.305: v67.31,64.14 67.95,64.14 67.95,81.92 67.31,82.55 67.31,86.36 68.58,87.63 E11.2 68.58,95.25 67.31,96.52 v67.31,119.38 | E8.4 v63.5,64.14 | v40.64,50.8 v40.64,58.42
AS2  (via drill 0.71)
  Top 0.305: 28.58,51.44 32.39,51.44 33.02,52.07 E7.12 | 28.58,51.44 27.94,52.07 E7.10 | v33.02,42.55 71.76,42.55 73.66,40.64 88.9,40.64 89.54,40.01 90.81,40.01 91.44,39.37 E6.6 | v15.24,51.44 28.58,51.44
  Bottom 0.305: E7.12 v33.02,42.55 | v15.24,51.44 15.24,49.53 13.97,49.53 EDGE.AS2
AT2  (via drill 0.71)
  Top 0.305: v15.24,53.98 22.23,53.98 E7.8
  Bottom 0.305: v15.24,53.98 15.24,53.34 13.97,52.07 EDGE.AT2
AU2  (via drill 0.71)
  Top 0.305: v33.02,55.88 17.78,55.88 17.15,56.52 v15.24,56.52
  Bottom 0.305: v15.24,56.52 13.97,55.24 EDGE.AU2 | v33.02,55.88 E7.3
AV2  (via drill 0.71)
  Top 0.305: v15.24,58.42 19.05,58.42 19.69,59.05 24.77,59.05 25.4,59.69 E7.6
  Bottom 0.305: v15.24,58.42 13.97,58.42 EDGE.AV2
BA1  (via drill 0.71)
  Top 0.305: v73.66,114.3 v93.98,114.3 | v18.42,74.93 13.97,74.93 EDGE.BA1 | v72.39,128.91 71.76,128.27 38.74,128.27 v38.1,128.91
  Bottom 0.305: E14.22 v73.66,114.3 72.39,115.57 v72.39,128.91 | v93.98,114.3 E15.5 | v18.42,74.93 18.42,106.68 17.78,107.31 17.78,114.3 19.05,115.57 19.05,120.65 19.69,121.28 38.1,121.28 | 38.1,121.28 E13.1 | 38.1,121.28 v38.1,128.91
BB1  (via drill 0.71)
  Top 0.305: v35.56,78.11 32.39,78.11 31.75,78.74 17.78,78.74 17.15,78.11 13.97,78.11 EDGE.BB1 | v66.04,102.23 69.22,102.23 70.49,103.5 88.27,103.5 88.9,102.87 99.7,102.87 v100.33,102.23 | v35.56,74.93 36.2,75.56 37.47,75.56 39.37,77.47 73.03,77.47 73.66,76.83 74.93,76.83 77.47,79.38 99.7,79.38 v100.33,78.74
  Bottom 0.305: E10.15 v35.56,78.11 v35.56,74.93 | v100.33,102.23 100.33,82.55 100.97,81.92 100.97,78.74 | 100.97,78.74 102.24,77.47 102.24,61.59 E9.2 | v66.04,102.23 E14.19 | v100.33,78.74 100.97,78.74
BC1  (via drill 0.71)
  Top 0.305: EDGE.BC1 13.97,79.38 14.61,78.74 16.51,78.74 17.15,79.38 v33.02,79.38 52.07,79.38 53.98,81.28 v72.39,81.28 | v66.68,56.52 67.95,56.52 68.58,57.15 v72.39,57.15 74.93,57.15 75.57,57.78 82.55,57.78 83.82,56.52 100.33,56.52 100.97,55.88 v104.14,55.88
  Bottom 0.305: v33.02,79.38 E10.14 | v66.68,56.52 66.68,53.98 E8.12 | v104.14,55.88 E9.1 | v72.39,57.15 v72.39,81.28 72.39,85.09 71.12,86.36 E11.1
BD1  (via drill 0.71)
  Top 0.305: 24.77,81.92 25.4,82.55 E10.11 | 24.77,81.92 14.61,81.92 13.97,82.55 EDGE.BD1 | 24.77,81.92 38.74,81.92 40.64,83.82 52.71,83.82 54.61,81.92 67.95,81.92 68.58,82.55 E11.13 | v105.41,99.69 98.43,99.69 97.79,99.06 70.49,99.06 v69.85,99.69
  Bottom 0.305: E8.3 68.58,63.5 E11.13 68.58,86.36 69.22,87 69.22,89.53 69.85,90.17 v69.85,99.69 | v105.41,99.69 105.41,113.03 104.14,114.3 E15.1
BE1  (via drill 0.71)
  Top 0.305: v90.17,104.78 65.41,104.78 64.77,104.14 v58.42,104.14 | E13.15 35.56,110.49 36.2,109.86 57.79,109.86 58.42,109.22 E14.16 | v33.66,87.63 13.97,87.63 EDGE.BE1
  Bottom 0.305: v90.17,104.78 90.17,58.42 90.81,57.78 90.81,53.98 E9.9 | E14.16 v58.42,104.14 | v33.66,87.63 34.29,88.27 34.29,106.05 35.56,107.31 E13.15
BF1  (via drill 0.71)
  Top 0.305: EDGE.BF1 13.97,88.9 v22.23,88.9 v24.13,88.9 | 69.22,104.14 v68.58,103.5 | 69.22,104.14 88.9,104.14 89.54,103.5 v102.87,103.5 | v24.13,102.23 56.52,102.23 57.15,102.87 64.77,102.87 66.04,104.14 69.22,104.14
  Bottom 0.305: v22.23,88.9 22.23,84.45 E10.10 | v102.87,103.5 102.87,113.67 101.6,114.94 E15.2 | v68.58,103.5 E14.20 | v24.13,88.9 v24.13,102.23
BH1  (via drill 0.71)
  Top 0.305: v35.56,94.61 34.93,93.98 27.31,93.98 26.67,94.61 14.61,94.61 13.97,93.98 EDGE.BH1 | v66.04,79.38 v69.85,79.38 | v101.6,57.15 84.46,57.15 83.19,58.42 v71.12,58.42 | v35.56,87 37.47,87 38.1,86.36 52.71,86.36 53.34,87 v66.04,87
  Bottom 0.305: v35.56,94.61 E10.2 v35.56,87 | v69.85,79.38 69.22,78.74 69.22,62.87 E8.1 v71.12,58.42 | v66.04,79.38 E11.12 v66.04,87 | v101.6,57.15 E9.13
BJ1
  Top 0.305: 60.96,93.98 42.55,93.98 41.91,93.34 29.85,93.34 E10.5 | 60.96,93.98 E11.4 | 89.54,93.98 60.96,93.98 | 89.54,93.98 106.68,93.98 106.68,107.31 104.78,109.22 104.14,109.22 E15.13 | 89.54,93.98 87,96.52 85.73,96.52 84.46,95.25 50.8,95.25 48.9,97.16 32.39,97.16 31.12,95.89 13.97,95.89 EDGE.BJ1
  Bottom 0.305: E8.2 66.04,58.42 66.04,57.78 65.41,57.15 62.23,57.15 62.23,88.9 63.5,90.17 E11.4
BK1  (via drill 0.71)
  Top 0.305: EDGE.BK1 13.97,98.42 v25.4,98.42 v53.34,98.42 v99.06,98.42
  Bottom 0.305: v25.4,98.42 E10.6 | v53.34,98.42 E14.14 | v99.06,98.42 E15.12
BL1  (via drill 0.71)
  Top 0.305: E1.2 35.56,19.05 36.2,19.68 73.66,19.68 75.57,17.78 86.36,17.78 88.27,15.88 100.97,15.88 101.6,16.51 E3.2 | v25.4,103.5 13.97,103.5 EDGE.BL1 | v57.15,99.69 52.71,99.69 52.07,99.06 26.67,99.06 v25.4,100.33 | v36.83,45.72 37.47,46.35 56.52,46.35 v57.15,45.72
  Bottom 0.305: E13.11 v25.4,103.5 v25.4,100.33 | v57.15,99.69 57.15,87.63 58.42,86.36 E11.9 58.42,63.5 57.15,62.23 57.15,57.78 58.42,56.52 E8.9 58.42,46.99 v57.15,45.72 | v36.83,45.72 36.83,27.3 35.56,26.04 E1.2
BS1  (via drill 0.71)
  Top 0.305: v25.4,115.57 16.51,115.57 14.61,117.47 13.97,117.47 EDGE.BS1 | v73.66,64.14 74.3,64.77 91.44,64.77 93.98,62.23 E9.5 | v26.67,97.16 26.67,97.79 52.07,97.79 52.71,97.16 53.98,97.16 54.61,97.79 71.76,97.79 v72.39,97.16
  Bottom 0.305: E13.6 v25.4,115.57 26.67,114.3 v26.67,97.16 | v73.66,64.14 73.03,64.77 73.03,80.01 73.66,80.64 73.66,81.92 73.03,82.55 73.03,85.72 72.39,86.36 v72.39,97.16 72.39,102.23 71.12,103.5 E14.21
BU2  (via drill 0.71)
  Top 0.305: v16.51,128.27 19.05,128.27 19.69,127.64 74.3,127.64 v74.93,128.27
  Bottom 0.305: v16.51,128.27 16.51,125.73 13.97,125.73 EDGE.BU2 | v74.93,128.27 74.93,111.12 76.2,109.86 E14.23
BV2  (via drill 0.71)
  Top 0.305: v78.11,127.64 77.47,127 v15.24,127
  Bottom 0.305: v78.11,127.64 78.11,123.83 E14.1 | v15.24,127 13.97,127 EDGE.BV2
GND  (via drill 0.71)
  Top 0.508: v50.8,118.11 C13.2 40.01,118.11 38.74,116.84 v20.32,116.84 | 88.9,120.65 90.17,121.92 v93.98,121.92 | C14.2 v109.22,124.46 | v50.8,120.65 88.9,120.65 | 88.9,120.65 E15.7 | E13.8 20.32,120.65 13.97,120.65 EDGE.BT1 | v20.32,60.96 E7.7 | v15.88,91.44 E10.8 | C16.- v17.15,68.58 | v20.32,52.7 13.97,52.7 EDGE.AT1 | v21.59,107.95 v19.05,107.95 | v20.32,17.78 E1.7 | v15.88,5.08 C17.- | C1.2 55.88,16.51 E2.7 | v76.2,19.05 88.9,19.05 E3.7 | v88.9,14.61 100.97,14.61 101.6,15.24 104.78,15.24 106.05,16.51 C3.2 | v55.88,13.97 v76.2,13.97 | v22.86,14.61 28.58,14.61 29.21,13.97 v43.18,13.97 | E12.7 84.46,91.44 83.19,90.17 C11.2 73.03,90.17 71.76,88.9 63.5,88.9 62.87,88.27 v55.88,88.27 | v88.9,88.27 100.97,88.27 101.6,88.9 104.78,88.9 106.05,90.17 C12.2 | E6.7 88.9,39.37 v76.2,39.37 73.66,39.37 71.76,41.27 v62.23,41.27 v55.88,41.27 | v88.9,34.92 95.89,34.92 96.52,35.56 104.78,35.56 106.05,36.83 C6.2 | C8.2 83.19,59.69 84.46,60.96 E9.7 | v88.9,58.42 104.78,58.42 106.05,59.69 C9.2 | v22.86,35.56 39.37,35.56 40.64,36.83 C4.2 55.88,36.83 E5.7 | v43.18,92.71 55.88,92.71 E11.7 | 64.14,55.24 63.5,54.61 E8.11 | 64.14,55.24 67.95,55.24 | 67.95,55.24 68.58,54.61 E8.13 | C7.2 50.17,59.69 51.44,60.96 E8.7 | 64.14,55.24 v57.15,55.24 | v76.2,56.52 75.57,55.88 68.58,55.88 67.95,55.24 | E4.7 v19.69,38.1
  Bottom 0.508: v50.8,118.11 v50.8,120.65 E14.12 | v93.98,121.92 C14.2 | v109.22,124.46 C15.2 | C16.- v20.32,60.96 v20.32,52.7 19.69,52.07 v19.69,38.1 | 15.88,81.92 v15.88,91.44 | 15.88,81.92 13.97,80.01 EDGE.BC2 | v17.15,68.58 17.15,80.64 15.88,81.92 | v19.05,107.95 19.05,114.3 20.32,115.57 v20.32,116.84 E13.8 | v21.59,107.95 21.59,92.71 E10.8 | C17.- v20.32,17.78 | v15.88,5.08 15.88,8.26 13.97,10.16 EDGE.AC2 | E3.7 v88.9,14.61 | E2.7 v55.88,13.97 | v76.2,13.97 C2.2 v76.2,19.05 76.2,26.04 77.47,27.3 77.47,34.29 76.2,35.56 C5.2 v76.2,39.37 | E1.7 v22.86,14.61 | v43.18,13.97 C1.2 | E12.7 v88.9,88.27 | E6.7 v88.9,34.92 | E9.7 v88.9,58.42 | v22.86,35.56 E4.7 | v43.18,92.71 C10.2 | v57.15,55.24 57.15,56.52 55.88,57.78 E8.7 55.88,62.23 57.15,63.5 57.15,86.36 55.88,87.63 v55.88,88.27 E11.7 | v62.23,41.27 62.23,52.07 E8.11 | v55.88,41.27 E5.7 | v76.2,56.52 C8.2
  pour Bottom (isolate 0.508): 15.24,0 15.24,132.08 125.73,132.08 125.73,0
  pour Top (isolate 0.508): 15.24,0 15.24,132.08 125.73,132.08 125.73,0
N$1
  Top 0.305: E1.3 35.56,20.32 93.98,20.32 E3.4 97.16,17.14 98.43,17.14 E3.3
N$4  (via drill 0.71)
  Top 0.305: v60.96,111.76 64.14,111.76 65.41,110.49 80.01,110.49 80.65,109.86 90.81,109.86 91.44,110.49 E15.9 | v53.98,12.06 57.79,12.06 58.42,11.43 E2.9 | v47.63,106.05 60.33,106.05 60.96,106.68 E14.17
  Bottom 0.305: E14.17 v60.96,111.76 | v53.98,12.06 53.98,62.87 55.25,64.14 55.25,81.92 54.61,82.55 54.61,90.17 48.26,96.52 48.26,105.41 v47.63,106.05
N$5  (via drill 0.71)
  Top 0.305: v27.94,24.77 v33.02,24.77 | v63.5,15.24 29.21,15.24 27.94,16.51 E1.5 | v101.6,27.3 87.63,27.3 87,26.67 64.14,26.67 v63.5,27.3
  Bottom 0.305: E4.2 35.56,36.2 33.02,33.66 E4.12 v33.02,24.77 | E1.5 v27.94,24.77 | v63.5,15.24 E2.4 v63.5,27.3 | v101.6,27.3 E6.13
N$6  (via drill 0.71)
  Top 0.305: v48.9,28.57 36.2,28.57 35.56,29.21 E4.13 | v45.72,121.92 35.56,121.92 34.29,120.65 33.02,120.65 E13.3
  Bottom 0.305: v48.9,28.57 48.26,29.21 48.26,63.5 49.53,64.77 49.53,66.04 48.26,67.31 48.26,89.53 48.9,90.17 48.9,92.71 45.09,96.52 45.09,114.3 45.72,114.94 v45.72,121.92
N$7  (via drill 0.71)
  Top 0.305: v29.85,58.42 30.48,59.05 39.37,59.05 45.72,65.41 45.72,66.04 46.36,66.67 48.9,66.67 49.53,66.04 93.35,66.04 111.13,83.82 111.13,125.73 93.98,125.73 89.54,130.18 59.69,130.18 58.42,128.91 40.64,128.91 v40.01,129.54
  Bottom 0.305: v29.85,58.42 29.21,57.78 29.21,29.21 30.48,27.94 E1.4 | v40.01,129.54 40.01,118.11 36.83,114.94 30.48,114.94 E13.4
N$8  (via drill 0.71)
  Top 0.305: v27.94,100.33 28.58,99.69 38.74,99.69 v39.37,100.33
  Bottom 0.305: v39.37,100.33 39.37,82.55 40.01,81.92 40.01,59.69 36.83,56.52 36.83,48.9 38.1,47.62 E4.1 | v27.94,100.33 E13.12
N$9
  Bottom 0.305: E4.4 30.48,39.37 31.75,40.64 31.75,109.22 30.48,110.49 E13.13
N$10
  Bottom 0.305: E9.12 99.06,52.07 100.33,50.8 100.33,21.59 97.79,19.05 97.79,15.88 93.98,12.06 85.73,12.06 85.73,20.32 83.19,22.86 83.19,104.78 81.28,106.68 81.28,127.64 78.74,130.18 59.69,130.18 59.69,113.03 55.88,109.22 E14.15
N$11  (via drill 0.71)
  Top 0.305: v90.17,41.27 90.17,40.64 102.24,40.64 v102.87,41.27
  Bottom 0.305: v90.17,41.27 90.17,19.05 E3.6 | v102.87,41.27 102.87,78.11 101.6,79.38 E12.13
N$12
  Bottom 0.305: E1.12 26.67,16.51 26.67,54.61 28.58,56.52 28.58,59.05 29.21,59.69 29.21,113.03 30.48,114.3 41.91,114.3 41.91,120.02 46.99,125.09 57.15,125.09 57.15,111.76 54.61,109.22 54.61,104.14 60.96,97.79 E11.5
N$13  (via drill 0.71)
  Top 0.305: v91.44,125.73 74.93,125.73 73.66,124.46 E14.3
  Bottom 0.305: v91.44,125.73 E15.6
N$14
  Top 0.305: E12.9 93.35,85.72 97.16,85.72 E12.12 | E12.5 95.89,89.53 99.7,89.53 E12.2
  Bottom 0.305: E12.9 91.44,85.09 93.98,87.63 E12.5 | E12.12 E9.3 | E14.7 65.41,125.09 69.85,125.09 69.85,111.76 72.39,109.22 72.39,103.5 77.47,98.42 77.47,35.56 82.55,30.48 82.55,13.97 91.44,5.08 106.68,5.08 106.68,91.44 104.78,93.34 101.6,93.34 E12.2
N$15  (via drill 0.71)
  Top 0.305: v97.79,81.92 v102.87,81.92
  Bottom 0.305: v97.79,81.92 98.43,81.28 98.43,62.87 97.79,62.23 97.79,54.61 E9.11 | v102.87,81.92 102.87,87.63 104.14,88.9 E12.1
N$16  (via drill 0.71)
  Top 0.305: v95.25,55.24 89.54,55.24 88.9,54.61 E9.8
  Bottom 0.305: v95.25,55.24 95.25,62.87 93.98,64.14 93.98,78.11 94.62,78.74 94.62,81.92 95.25,82.55 95.25,86.36 96.52,87.63 E12.4
N$17
  Bottom 0.305: E9.6 91.44,62.23 93.35,64.14 93.35,83.19 E12.10
N$18
  Top 0.305: E14.2 78.11,125.09 81.92,125.09 83.82,123.19 97.79,123.19 100.33,120.65 100.33,109.22 80.01,109.22 79.38,109.86 60.96,109.86 59.69,111.12 59.69,113.03 81.28,113.03 82.55,111.76 E15.8
N$19  (via drill 0.71)
  Top 0.305: v97.16,100.33 97.16,99.69 71.76,99.69 70.49,100.97 v62.23,100.97
  Bottom 0.305: v97.16,100.33 97.79,99.69 97.79,90.17 97.16,89.53 97.16,87 96.52,86.36 E12.11 | v62.23,100.97 62.23,117.47 60.96,118.75 E14.8
N$20  (via drill 0.71)
  Top 0.305: v68.58,118.11 69.22,118.75 85.09,118.75 87,116.84 v99.06,116.84
  Bottom 0.305: v68.58,118.11 E14.5 | v99.06,116.84 E15.3
N$21  (via drill 0.71)
  Top 0.305: v71.12,115.57 74.3,115.57 74.93,114.94 92.71,114.94 93.35,115.57 v96.52,115.57
  Bottom 0.305: v71.12,115.57 E14.4 | v96.52,115.57 E15.11
N$22  (via drill 0.71)
  Top 0.305: v80.01,127 79.38,126.36 74.3,126.36 73.03,125.09 66.68,125.09 66.04,124.46 E14.6 | v80.01,83.82 E12.8
  Bottom 0.305: v80.01,83.82 v80.01,127
N$23
  Bottom 0.305: E14.9 58.42,124.46 59.06,125.09 59.06,130.81 90.17,130.81 90.17,106.68 91.44,105.41 E12.6
N$24  (via drill 0.71)
  Top 0.305: v99.06,96.52 97.79,97.79 74.93,97.79 73.03,95.89 71.76,95.89 70.49,97.16 55.25,97.16 54.61,96.52 v51.44,96.52
  Bottom 0.305: E14.10 55.25,122.56 53.98,122.56 E14.11 52.07,121.92 52.07,97.16 v51.44,96.52 | v99.06,96.52 E12.3
N$25  (via drill 0.71)
  Top 0.305: v26.67,89.53 29.85,89.53 30.48,90.17 E10.4
  Bottom 0.305: v26.67,89.53 26.67,82.55 27.31,81.92 27.31,62.87 26.67,62.23 26.67,55.88 26.04,55.24 26.04,53.98 E7.9
N$26  (via drill 0.71)
  Top 0.305: v45.72,55.88 38.1,55.88 37.47,55.24 36.2,55.24 35.56,54.61 E7.13 | v44.45,88.9 34.29,88.9 33.02,90.17 E10.3
  Bottom 0.305: v45.72,55.88 45.72,70.48 44.45,71.75 v44.45,88.9
N$27
  Top 0.305: E7.5 28.58,60.33 29.85,60.33 E7.4
  Bottom 0.305: E7.5 E10.12
N$28  (via drill 0.71)
  Top 0.305: E7.2 E7.1 | v34.29,85.72 31.12,85.72 30.48,85.09 E10.13
  Bottom 0.305: v34.29,85.72 34.29,74.3 36.2,72.39 36.2,61.59 E7.2
N$33
  Top 0.305: E2.10 63.5,12.7 88.9,12.7 E3.9
N$43
  Bottom 0.305: E5.4 63.5,50.8 64.77,52.07 64.77,54.61 62.87,56.52 60.96,56.52 E8.5
N$44
  Bottom 0.305: E5.3 66.04,36.83 62.23,33.02 62.23,16.51 61.6,15.88 57.15,15.88 57.15,43.81 59.69,46.35 59.69,56.52 58.42,57.78 E8.6
N$45  (via drill 0.71)
  Top 0.305: E1.10 27.94,8.89 28.58,8.26 34.93,8.26 35.56,8.89 E1.13 35.56,11.43 36.83,12.7 v40.64,12.7 | v41.28,35.56 55.88,35.56 56.52,36.2 57.79,36.2 58.42,36.83 E5.6
  Bottom 0.305: v41.28,35.56 40.64,34.92 v40.64,12.7
N$46  (via drill 0.71)
  Top 0.305: v24.13,20.95 24.77,21.59 35.56,21.59 36.2,20.95 57.79,20.95 v58.42,21.59
  Bottom 0.305: v24.13,20.95 24.13,14.61 24.77,13.97 24.77,10.79 E1.9 | v58.42,21.59 E2.6
VCC  (via drill 0.71)
  Top 0.508: E9.14 104.14,54.61 C9.1 | E3.14 104.14,11.43 C3.1 | 104.14,31.75 C6.1 | E8.14 71.12,54.61 C8.1 | E2.14 71.12,11.43 C2.1 | E5.14 71.12,31.75 C5.1 85.73,31.75 86.36,32.38 103.51,32.38 104.14,31.75 | E4.14 38.1,31.75 C4.1 | E1.14 38.1,11.43 C1.1 | v17.15,1.27 v43.18,1.27 v71.12,1.27 | 104.14,31.75 E6.14 | E15.14 104.14,113.03 C15.1 | E12.14 104.14,85.09 C12.1 | 71.12,85.09 C11.1 v78.74,85.09 | v84.46,124.46 C14.1 | E14.24 v84.46,107.95 v104.14,107.95 | v78.74,87 v104.14,87 | E13.16 38.1,113.03 C13.1 | E10.16 38.1,85.09 C10.1 52.71,85.09 53.34,85.72 70.49,85.72 71.12,85.09 | E7.14 38.1,54.61 C7.1 | v15.88,80.01 16.51,80.64 v38.1,80.64 | 71.12,85.09 E11.14
  Bottom 0.508: E3.14 105.41,11.43 105.41,24.77 104.14,26.04 E6.14 104.14,33.66 105.41,34.92 105.41,41.27 104.14,42.55 E9.14 | C2.1 75.57,11.43 74.93,12.06 74.93,26.04 76.2,27.3 C5.1 76.2,34.29 74.93,35.56 74.93,40.01 76.2,41.27 C8.1 | C1.1 C17.+ v43.18,1.27 | E1.14 38.1,13.34 39.37,14.61 39.37,20.95 38.1,22.23 E4.14 39.37,31.75 39.37,47.62 38.1,48.9 E7.14 | v17.15,1.27 17.15,2.54 16.51,3.17 16.51,3.81 13.97,3.81 EDGE.AA2 | v71.12,1.27 E2.14 | v78.74,85.09 v78.74,87 E14.24 | v84.46,107.95 v84.46,124.46 | v104.14,87 E12.14 | v104.14,107.95 E15.14 | C7.1 42.55,54.61 41.91,55.24 41.91,62.87 43.18,64.14 C16.+ C10.1 43.18,87 41.91,88.27 41.91,93.34 43.18,94.61 C13.1 | v15.88,80.01 15.88,74.3 13.97,74.3 EDGE.BA2 | E10.16 v38.1,80.64

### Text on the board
Bottom: VRS | TU10 CRC AND WRITE GATING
